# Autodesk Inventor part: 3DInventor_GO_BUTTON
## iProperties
Created: 2006-11
Part Number: 3DInventor_GO_BUTTON
Document SubType Name: Modeling
Designer: conardl1
Density: 1 g/cm^3
DESCRIPTION: Go Button Part
MODELED_BY: L Conard
Author: conardl1
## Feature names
1. Base1
